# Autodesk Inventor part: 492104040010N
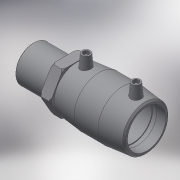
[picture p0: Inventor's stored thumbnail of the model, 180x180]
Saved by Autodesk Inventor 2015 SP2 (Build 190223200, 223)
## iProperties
Created: 2017-06
Part Number: 492104040010N
Material: Generic
Description: PLASSON Male Transition Coupler 40 x 1"
Document SubType Name: Modeling
Designer: KIM
Mass: 178.779 g
Surface Area: 447.66 cm^2
Volume: 178.779 cm^3
Density: 1 g/cm^3
Appearance: Default
Author: KIM
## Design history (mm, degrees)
derived "492104.ipt"
feature "Solid1::492104.ipt"
tag "TaggingFeature1"
body "Solid1"
other parameters: "d0" = 98, "d2" = 56, "d3" = 48, "d4" = 32.66667, "d5" = 50.4, "d6" = 38, "d8" = 168 deg, "d10" = 19.2, "d11" = 6.4, "d29" = 46, "d30" = 14, "d31" = 34.3, "d34" = 5 deg, "d41" = 4, "d42" = 14, "d43" = 0, "d48" = 3, "d49" = 0, "d57" = 22, "d58" = 33.249, "d59" = 26.5992, "d60" = 40.5, "d61" = 56, "d62" = 0.66498, "d65" = 1.68, "d70" = 0.1, "d71" = 45, "d72" = 11.25, "d73" = 19.2, "d75" = 0, "L_" = 143, "L_1" = 48, "D_1" = 56, "A_" = 46, "d_2" = 12, "L_2" = 45, "D_" = 22, "R_" = 33.249
